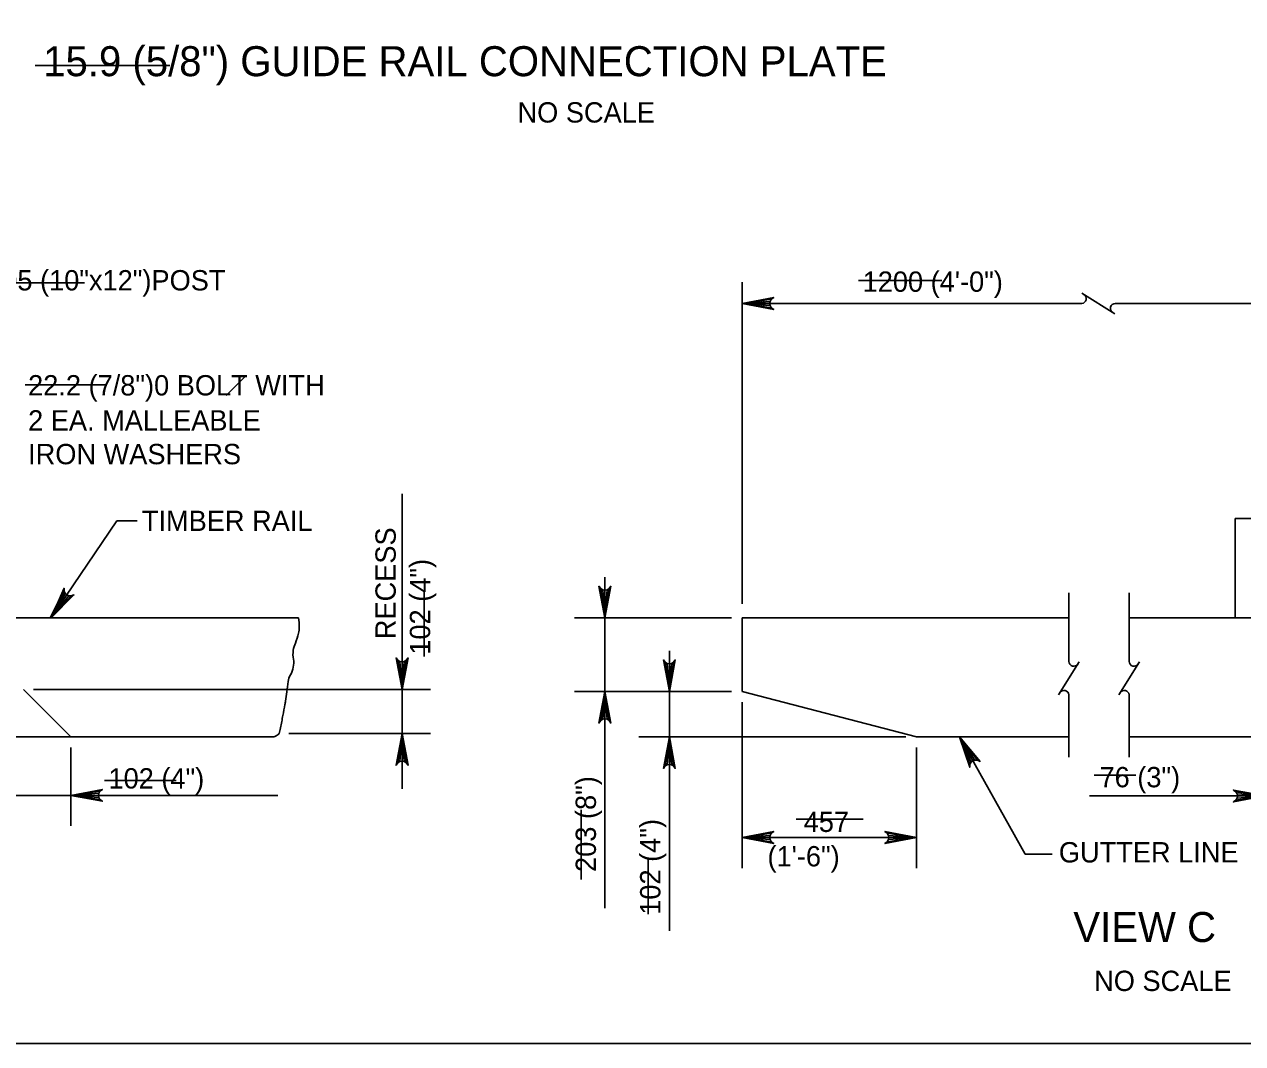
# Model space of a CAD drawing. Extents: x 179 to 454, y -271 to 54.
# Drawn here: x 373.93 to 381.12, y -21.25 to -15.23 of the extents above; entities that cross this region are included whole.
import ezdxf

# ---------------------------------------------------------------- set-up
doc = ezdxf.new("R2010")
doc.units = 0
for name, color, linetype in [('Level 1', 7, 'Continuous'), ('Level 2', 7, 'Continuous'), ('Level 3', 7, 'Continuous'), ('Level 41', 7, 'Continuous')]:
    doc.layers.add(name, color=color, linetype=linetype)

msp = doc.modelspace()

# ---------------------------------------------------------------- linework, layer by layer
at = {"layer": 'Level 1'}
msp.add_lwpolyline([(362.5132, -21.25), (394.0132, -21.25), (394.0132, -0.75), (362.5132, -0.75)], close=True, dxfattribs=at)
at = {"layer": 'Level 2'}
for p, q in [((380.3668, -16.9415), (380.1712, -16.8187)), ((380.1717, -16.8801), (378.1659, -16.8801)), ((381.4291, -16.8801), (380.369, -16.8801)), ((381.0776, -18.1498), (381.7805, -18.1498)), ((381.0776, -18.7356), (381.0776, -18.1498)), ((380.0952, -18.5877), (380.0952, -18.9929)), ((380.4507, -18.5877), (380.4507, -18.9929)), ((370.6053, -18.7351), (375.5468, -18.7351)), ((378.1659, -18.7356), (380.0952, -18.7356)), ((378.1659, -18.7356), (378.1659, -19.1706)), ((380.4507, -18.7356), (383.0938, -18.7356)), ((380.1567, -18.9952), (380.0338, -19.1907)), ((380.5122, -18.9952), (380.3893, -19.1907)), ((374.2022, -19.4385), (373.9224, -19.1587)), ((378.1659, -19.1706), (379.1952, -19.4385)), ((380.0952, -19.1902), (380.0952, -19.5587)), ((380.4507, -19.1902), (380.4507, -19.5587)), ((368.4912, -19.4385), (374.2022, -19.4385)), ((374.2022, -19.4385), (375.4007, -19.4385)), ((379.1952, -19.4385), (380.0952, -19.4385)), ((380.4507, -19.4385), (382.9477, -19.4385))]:
    msp.add_line(p, q, dxfattribs=at)
for centre, radius, start, end in [((380.169, -16.8514), 0.0289, 275.32859, 57.86724), ((380.369, -16.909), 0.0289, 90, 240), ((375.1425, -18.792), 0.4083, 0, 8.01238), ((375.2116, -18.7509), 0.3437, 337.02806, 347.1491), ((375.3916, -18.792), 0.1591, 347.1491, 0), ((375.6946, -18.9557), 0.1809, 157.02806, 170.99701), ((375.6729, -18.9522), 0.1589, 170.99701, 190.43044), ((375.3998, -19.0025), 0.1188, 347.91871, 10.43044), ((375.3567, -18.9933), 0.1629, 330.90022, 347.91871), ((380.1241, -18.9929), 0.0289, 180, 330), ((380.4795, -18.9929), 0.0289, 180, 330), ((376.3603, -19.2578), 0.8871, 170.53428, 174.54526), ((375.6062, -19.1321), 0.1227, 150.90022, 170.53428), ((374.8018, -19.109), 0.6784, 349.9584, 354.54526), ((380.0665, -19.193), 0.0289, 5.32859, 147.86724), ((380.4219, -19.193), 0.0289, 5.32859, 147.86724), ((333.5978, -11.636), 42.5547, 349.60825, 349.69526), ((370.8885, -18.4161), 4.6526, 349.69526, 349.95839), ((372.9599, -18.8544), 2.5362, 347.90537, 349.60825), ((375.4213, -19.4167), 0.0105, 301.64147, 344.21336), ((374.9121, -19.2728), 0.5397, 344.21336, 347.90537), ((375.3466, -19.2955), 0.1529, 290.70356, 301.64147)]:
    msp.add_arc(centre, radius, start, end, dxfattribs=at)
at = {"layer": 'Level 3'}
for p, q in [((378.1659, -18.6534), (378.1659, -16.7536)), ((375.1196, -17.4242), (375.238, -17.3058)), ((376.1581, -19.1587), (376.1581, -18.004)), ((374.087, -18.7351), (374.4749, -18.1632)), ((374.4749, -18.1632), (374.5949, -18.1632)), ((377.3557, -18.7356), (377.3557, -18.4956)), ((378.1034, -18.7356), (377.1757, -18.7356)), ((377.3557, -18.7356), (377.3557, -20.4508)), ((376.1582, -19.1587), (376.1582, -18.9336)), ((377.7361, -19.1706), (377.7361, -18.9306)), ((373.981, -19.1587), (376.3269, -19.1587)), ((376.1582, -19.1587), (376.1582, -19.7466)), ((378.1034, -19.1706), (377.1757, -19.1706)), ((378.1034, -19.1706), (377.5561, -19.1706)), ((377.7361, -19.1706), (377.7361, -20.5846)), ((378.1659, -19.2331), (378.1659, -20.2131)), ((377.3557, -19.2906), (377.3557, -19.4106)), ((375.4901, -19.4196), (376.3269, -19.4196)), ((379.1327, -19.4385), (377.5561, -19.4385)), ((379.4486, -19.4385), (379.8377, -20.1307)), ((374.2022, -19.501), (374.2022, -19.9642)), ((377.7361, -19.5585), (377.7361, -19.6785)), ((379.1952, -19.501), (379.1952, -20.2131)), ((373.8466, -19.7843), (375.4248, -19.7843)), ((381.0283, -19.7876), (380.2167, -19.7876)), ((381.2533, -19.7876), (381.0283, -19.7876)), ((379.1952, -20.0331), (378.1659, -20.0331)), ((379.8377, -20.1307), (379.9963, -20.1307))]:
    msp.add_line(p, q, dxfattribs=at)
for points in [[(378.1659, -16.8801), (378.3523, -16.8452), (378.338, -16.8551), (378.3306, -16.8676), (378.3284, -16.8801), (378.3306, -16.8926), (378.338, -16.9051), (378.3523, -16.915), (378.1659, -16.8801), (378.338, -16.9051), (378.3306, -16.8926), (378.1659, -16.8801), (378.3284, -16.8801), (378.3306, -16.8676), (378.1659, -16.8801), (378.338, -16.8551)], [(377.3557, -18.7356), (377.3207, -18.5492), (377.3307, -18.5635), (377.3432, -18.5709), (377.3557, -18.5731), (377.3682, -18.5709), (377.3807, -18.5635), (377.3906, -18.5492), (377.3557, -18.7356), (377.3807, -18.5635), (377.3682, -18.5709), (377.3557, -18.7356), (377.3557, -18.5731), (377.3432, -18.5709), (377.3557, -18.7356), (377.3307, -18.5635)], [(374.087, -18.7351), (374.1627, -18.5612), (374.1629, -18.5787), (374.1691, -18.5918), (374.1782, -18.6006), (374.1898, -18.6058), (374.2043, -18.6067), (374.2206, -18.6004), (374.087, -18.7351), (374.2043, -18.6067), (374.1898, -18.6058), (374.087, -18.7351), (374.1782, -18.6006), (374.1691, -18.5918), (374.087, -18.7351), (374.1629, -18.5787)], [(376.1582, -19.1587), (376.1232, -18.9722), (376.1332, -18.9866), (376.1457, -18.994), (376.1582, -18.9962), (376.1707, -18.994), (376.1832, -18.9866), (376.1931, -18.9722), (376.1582, -19.1587), (376.1832, -18.9866), (376.1707, -18.994), (376.1582, -19.1587), (376.1582, -18.9962), (376.1457, -18.994), (376.1582, -19.1587), (376.1332, -18.9866)], [(377.7361, -19.1706), (377.7012, -18.9842), (377.7111, -18.9985), (377.7236, -19.0059), (377.7361, -19.0081), (377.7486, -19.0059), (377.7611, -18.9985), (377.771, -18.9842), (377.7361, -19.1706), (377.7611, -18.9985), (377.7486, -19.0059), (377.7361, -19.1706), (377.7361, -19.0081), (377.7236, -19.0059), (377.7361, -19.1706), (377.7111, -18.9985)], [(377.3557, -19.1706), (377.3906, -19.357), (377.3807, -19.3427), (377.3682, -19.3352), (377.3557, -19.3331), (377.3432, -19.3352), (377.3307, -19.3427), (377.3207, -19.357), (377.3557, -19.1706), (377.3307, -19.3427), (377.3432, -19.3352), (377.3557, -19.1706), (377.3557, -19.3331), (377.3682, -19.3352), (377.3557, -19.1706), (377.3807, -19.3427)], [(376.1582, -19.4196), (376.1931, -19.606), (376.1832, -19.5917), (376.1707, -19.5843), (376.1582, -19.5821), (376.1457, -19.5843), (376.1332, -19.5917), (376.1232, -19.606), (376.1582, -19.4196), (376.1332, -19.5917), (376.1457, -19.5843), (376.1582, -19.4196), (376.1582, -19.5821), (376.1707, -19.5843), (376.1582, -19.4196), (376.1832, -19.5917)], [(377.7361, -19.4385), (377.771, -19.6249), (377.7611, -19.6106), (377.7486, -19.6032), (377.7361, -19.601), (377.7236, -19.6032), (377.7111, -19.6106), (377.7012, -19.6249), (377.7361, -19.4385), (377.7111, -19.6106), (377.7236, -19.6032), (377.7361, -19.4385), (377.7361, -19.601), (377.7486, -19.6032), (377.7361, -19.4385), (377.7611, -19.6106)], [(379.4486, -19.4385), (379.5704, -19.5838), (379.5547, -19.5762), (379.5402, -19.5759), (379.5283, -19.5802), (379.5184, -19.5882), (379.5111, -19.6007), (379.5095, -19.6181), (379.4486, -19.4385), (379.5111, -19.6007), (379.5184, -19.5882), (379.4486, -19.4385), (379.5283, -19.5802), (379.5402, -19.5759), (379.4486, -19.4385), (379.5547, -19.5762)], [(374.2022, -19.7843), (374.3887, -19.7493), (374.3743, -19.7592), (374.3669, -19.7718), (374.3648, -19.7843), (374.3669, -19.7967), (374.3743, -19.8092), (374.3887, -19.8192), (374.2022, -19.7843), (374.3743, -19.8092), (374.3669, -19.7967), (374.2022, -19.7843), (374.3648, -19.7843), (374.3669, -19.7718), (374.2022, -19.7843), (374.3743, -19.7592)], [(381.2533, -19.7876), (381.0669, -19.8225), (381.0813, -19.8126), (381.0887, -19.8001), (381.0908, -19.7876), (381.0887, -19.7751), (381.0813, -19.7626), (381.0669, -19.7527), (381.2533, -19.7876), (381.0813, -19.7626), (381.0887, -19.7751), (381.2533, -19.7876), (381.0908, -19.7876), (381.0887, -19.8001), (381.2533, -19.7876), (381.0813, -19.8126)], [(378.1659, -20.0331), (378.3523, -19.9982), (378.338, -20.0081), (378.3306, -20.0206), (378.3284, -20.0331), (378.3306, -20.0456), (378.338, -20.0581), (378.3523, -20.068), (378.1659, -20.0331), (378.338, -20.0581), (378.3306, -20.0456), (378.1659, -20.0331), (378.3284, -20.0331), (378.3306, -20.0206), (378.1659, -20.0331), (378.338, -20.0081)], [(379.1952, -20.0331), (379.0087, -20.068), (379.0231, -20.0581), (379.0305, -20.0456), (379.0327, -20.0331), (379.0305, -20.0206), (379.0231, -20.0081), (379.0087, -19.9982), (379.1952, -20.0331), (379.0231, -20.0081), (379.0305, -20.0206), (379.1952, -20.0331), (379.0327, -20.0331), (379.0305, -20.0456), (379.1952, -20.0331), (379.0231, -20.0581)]]:
    msp.add_lwpolyline(points, dxfattribs=at)
for points in [[(378.294, -16.8588), (378.294, -16.9014), (378.1659, -16.8801)], [(374.1683, -18.6507), (374.1362, -18.6268), (374.0807, -18.7351)], [(377.3357, -18.6156), (377.3757, -18.6156), (377.3557, -18.7356)], [(376.1393, -19.0461), (376.1769, -19.0461), (376.1582, -19.1587)], [(377.7161, -19.0506), (377.7561, -19.0506), (377.7361, -19.1706)], [(377.3357, -19.2906), (377.3757, -19.2906), (377.3557, -19.1706)], [(376.1393, -19.5321), (376.1769, -19.5321), (376.1582, -19.4196)], [(377.7161, -19.5585), (377.7561, -19.5585), (377.7361, -19.4385)], [(379.498, -19.5647), (379.5304, -19.5459), (379.4578, -19.4579)], [(374.3222, -19.7643), (374.3222, -19.8042), (374.2022, -19.7843)], [(378.2859, -20.0131), (378.2859, -20.0531), (378.1659, -20.0331)], [(379.0752, -20.0131), (379.0752, -20.0531), (379.1952, -20.0331)]]:
    msp.add_lwpolyline(points, close=True, dxfattribs=at)
at = {"layer": 'Level 41'}
for p, q in [((373.9919, -15.4751), (374.7861, -15.4751)), ((373.3977, -16.7574), (374.2822, -16.7574)), ((378.853, -16.7434), (379.3443, -16.7434)), ((373.9336, -17.3604), (374.4111, -17.3604)), ((376.2892, -18.9638), (376.2892, -18.5815)), ((374.4005, -19.6964), (374.8249, -19.6964)), ((380.2449, -19.6656), (380.4905, -19.6656)), ((377.2155, -20.2801), (377.2155, -19.8705)), ((378.4846, -19.9251), (378.8803, -19.9251)), ((377.6112, -20.4849), (377.6112, -20.1572))]:
    msp.add_line(p, q, dxfattribs=at)

# ---------------------------------------------------------------- texts
at = {"layer": 'Level 2'}
for s, height, p in [('15.9 (5/8") GUIDE RAIL CONNECTION PLATE', 0.177167, (374.039, -15.5381)), ('VIEW C', 0.17717, (380.1215, -20.6502))]:
    msp.add_text(s, height=height, dxfattribs=at).set_placement(p)
at = {"layer": 'Level 3'}
for s, p in [('NO SCALE', (376.8397, -15.8119)), ('C 254x305 (10"x12")POST', (373.1997, -16.803)), ('1200 (4\'-0")', (378.8774, -16.811)), ('22.2 (7/8")0 BOLT WITH', (373.9501, -17.423)), ('2 EA. MALLEABLE', (373.9501, -17.6302)), ('IRON WASHERS', (373.9501, -17.8292)), ('TIMBER RAIL', (374.6217, -18.2233)), ('102 (4")', (374.4247, -19.7438)), ('76 (3")', (380.2759, -19.7365)), ('457', (378.5293, -20.0002)), ('GUTTER LINE', (380.0359, -20.1803)), ('(1\'-6")', (378.3157, -20.2036)), ('NO SCALE', (380.2443, -20.9394))]:
    msp.add_text(s, height=0.12, dxfattribs=at).set_placement(p)
for s, p in [('RECESS', (376.1207, -18.8621)), ('102 (4")', (376.3241, -18.9537)), ('203 (8")', (377.3028, -20.2362)), ('102 (4")', (377.6832, -20.4892))]:
    msp.add_text(s, height=0.12, rotation=90, dxfattribs=at).set_placement(p)

doc.saveas('drawing.dxf')
